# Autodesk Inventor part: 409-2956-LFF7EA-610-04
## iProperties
Created: 2011-01
Part Number: 409-2956-LFF7EA-610-04
Cost Center: 0 lbmass
Material: A36 STEEL PLATE
Document SubType Name: Sheet Metal
Designer: S. Boerckel
Authority: 0 in^3
Mass: 821.115 g
Surface Area: 265.322 cm^2
Volume: 104.468 cm^3
Density: 7.86 g/cm^3
Flat Pattern Width: 17.78 cm
Flat Pattern Length: 8.89 cm
Flat Pattern Area: 158.064 cm^2
Sheet Metal Rule: 3/8"Thk
Description: GUSSET
SaveDate: 2008-01-15
SaveTime: 10:24
FileName: Sheet Metal
Wide: =<Flat Pattern Width>cm
Length: =<Flat Pattern Length>cm
Thickness: 0.3750 in
SMR: =<Sheet Metal Rule> - <Material>
Author: S. Boerckel
Revision Number: 0
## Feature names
1. Plate1
